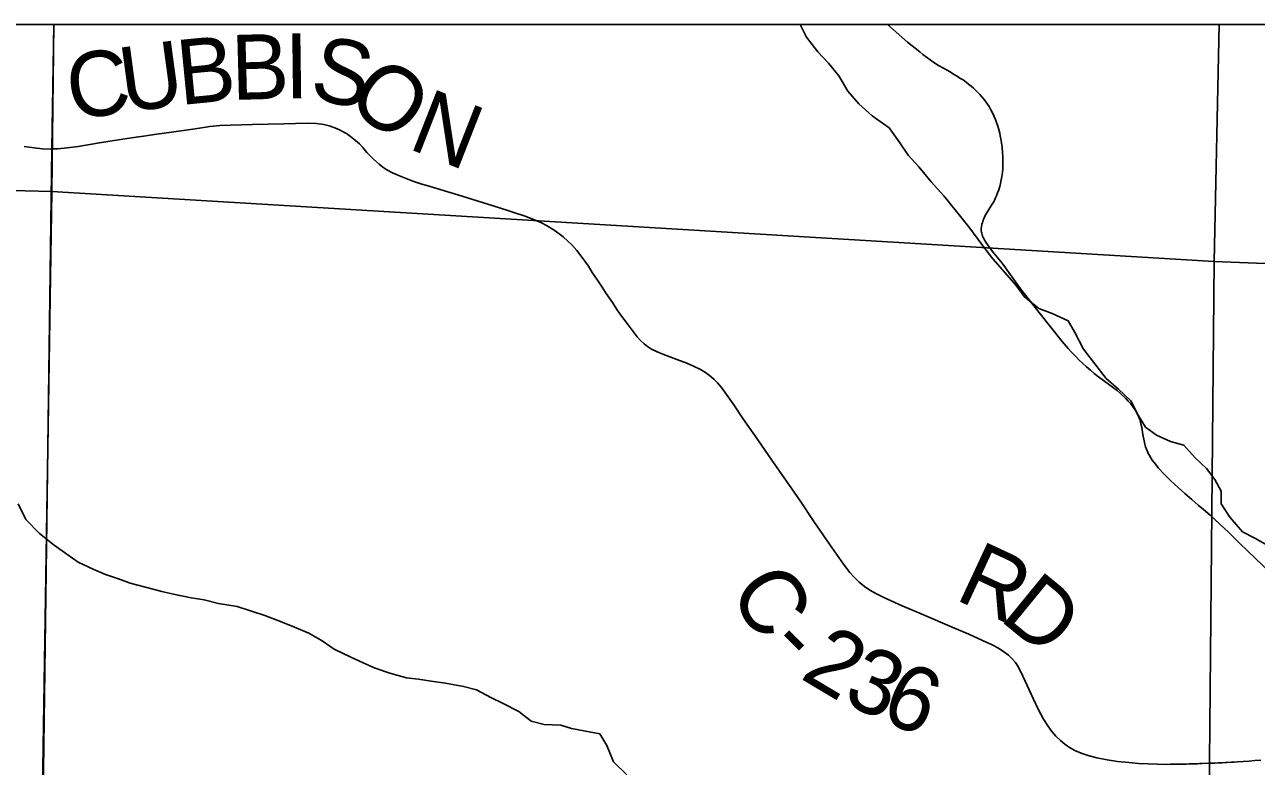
# Model space of a CAD drawing. Extents: x 0 to 34, y 0 to 22.
# Drawn here: x 3.363 to 4.44, y 20.252 to 20.9 of the extents above; entities that cross this region are included whole.
import ezdxf

# ---------------------------------------------------------------- set-up
doc = ezdxf.new("R2010")
doc.units = 0
for name, color, linetype in [('GM_X_Corporation', 7, 'Continuous'), ('GM_X_County_Road', 7, 'Continuous'), ('GM_X_County_Road_Text', 7, 'Continuous'), ('GM_X_Minor_River', 7, 'Continuous'), ('SH_Data', 7, 'Continuous')]:
    doc.layers.add(name, color=color, linetype=linetype)

msp = doc.modelspace()

# ---------------------------------------------------------------- linework, layer by layer
at = {"layer": 'GM_X_Corporation'}
for points in [[(8.9, 20.9), (2.1, 20.9), (2.1, 15.6606)], [(5.3543, 16.3597), (5.3699, 17.5116), (5.3717, 17.6123), (4.6401, 17.6298), (4.3705, 17.6391), (4.3669, 17.8198), (4.37, 17.9048), (4.3768, 18.4091), (4.3782, 18.6502), (4.377, 18.6713), (3.7035, 18.69), (3.3642, 18.7005), (3.3691, 19.5041), (3.3724, 19.7263), (3.3869, 20.7918), (3.3886, 20.9), (2.1, 20.9), (2.1, 15.6606)], [(8.9, 20.9), (3.3886, 20.9), (3.3869, 20.7918), (3.3724, 19.7263), (3.3691, 19.5041), (3.3642, 18.7005)]]:
    msp.add_lwpolyline(points, dxfattribs=at)
for points in [[(3.3885, 20.9), (2.378, 20.9), (2.3781, 20.7796), (3.3867, 20.754)], [(4.4076, 20.9), (3.3885, 20.9), (3.3867, 20.754), (4.4032, 20.6929)], [(5.4364, 20.9), (4.4076, 20.9), (4.4032, 20.6929), (5.4344, 20.6525)], [(3.3867, 20.754), (3.3708, 19.7265), (2.3578, 19.7506), (2.3781, 20.7796)], [(3.3867, 20.754), (4.4032, 20.6929), (4.3939, 19.6935), (3.3708, 19.7265)], [(5.4344, 20.6525), (5.4328, 20.6183), (5.4095, 19.6556), (4.3939, 19.6935), (4.4032, 20.6929)]]:
    msp.add_lwpolyline(points, close=True, dxfattribs=at)
at = {"layer": 'GM_X_County_Road'}
for points in [[(4.4522, 20.4211), (4.4256, 20.4464), (4.416, 20.456), (4.4078, 20.4636), (4.3995, 20.471), (4.3939, 20.476), (4.3892, 20.48), (4.3835, 20.4849), (4.3775, 20.4901), (4.3715, 20.4954), (4.3653, 20.5011), (4.3593, 20.5069), (4.3545, 20.5121), (4.3506, 20.5171), (4.349, 20.5192), (4.3477, 20.5212), (4.3466, 20.5232), (4.3455, 20.5251), (4.3447, 20.5269), (4.3439, 20.5288), (4.3432, 20.5309), (4.3425, 20.5332), (4.3419, 20.536), (4.3408, 20.5417), (4.3399, 20.5477), (4.3394, 20.5499), (4.3388, 20.5525), (4.3381, 20.5547), (4.3373, 20.5567), (4.3364, 20.5587), (4.3354, 20.5607), (4.3344, 20.5625), (4.3331, 20.5644), (4.3301, 20.5684), (4.328, 20.5709), (4.3259, 20.5731), (4.3213, 20.5774), (4.3183, 20.5801), (4.3151, 20.5826), (4.3021, 20.5921), (4.2983, 20.5951), (4.2949, 20.5979), (4.2915, 20.6008), (4.2884, 20.6036), (4.2852, 20.6067), (4.2818, 20.6101), (4.2784, 20.6137), (4.2755, 20.6169), (4.2703, 20.623), (4.2509, 20.6472), (4.2338, 20.669), (4.2177, 20.6914), (4.2105, 20.7003), (4.2076, 20.7039), (4.2047, 20.708), (4.2029, 20.7107), (4.202, 20.7123), (4.2012, 20.7138), (4.2006, 20.7151), (4.2002, 20.7165), (4.1999, 20.7176), (4.1997, 20.7187), (4.1995, 20.7198), (4.1995, 20.7209), (4.1995, 20.7219), (4.1996, 20.7229), (4.1997, 20.7239), (4.1999, 20.7249), (4.2001, 20.7259), (4.2004, 20.7268), (4.2007, 20.7278), (4.201, 20.7287), (4.2014, 20.7298), (4.2019, 20.7309), (4.2027, 20.7326), (4.2038, 20.7346), (4.2085, 20.7423), (4.2106, 20.7458), (4.2117, 20.748), (4.2128, 20.7503), (4.2138, 20.7529), (4.2147, 20.7555), (4.2156, 20.7584), (4.2163, 20.7611), (4.217, 20.7642), (4.2175, 20.7673), (4.218, 20.7708), (4.2183, 20.7739), (4.2184, 20.7773), (4.2184, 20.7811), (4.2183, 20.7846), (4.2181, 20.7882), (4.2177, 20.7927), (4.2172, 20.7966), (4.2166, 20.8002), (4.2161, 20.8027), (4.2156, 20.8051), (4.2148, 20.8083), (4.214, 20.8111), (4.2129, 20.8144), (4.2119, 20.8171), (4.2108, 20.8197), (4.2096, 20.8222), (4.2079, 20.8255), (4.2063, 20.8283), (4.2048, 20.8305), (4.2034, 20.8325), (4.2019, 20.8345), (4.2001, 20.8368), (4.1983, 20.8389), (4.1961, 20.8411), (4.1945, 20.8427), (4.1926, 20.8445), (4.1907, 20.8462), (4.1887, 20.8478), (4.1862, 20.8497), (4.1836, 20.8516), (4.1808, 20.8533), (4.1778, 20.8552), (4.1752, 20.8568), (4.1722, 20.8586), (4.1665, 20.8618), (4.1622, 20.8643), (4.1581, 20.867), (4.1548, 20.8693), (4.1515, 20.8716), (4.1485, 20.8738), (4.1456, 20.8761), (4.1351, 20.8848), (4.1174, 20.9)], [(4.444, 20.257), (4.4387, 20.2566), (4.4338, 20.2562), (4.4285, 20.2558), (4.4236, 20.2554), (4.4207, 20.2553), (4.4183, 20.2552), (4.4141, 20.2549), (4.4129, 20.2548), (4.4101, 20.2547), (4.4084, 20.2546), (4.4066, 20.2545), (4.4037, 20.2544), (4.3994, 20.2542), (4.3927, 20.254), (4.3903, 20.2539), (4.3885, 20.2538), (4.386, 20.2537), (4.3848, 20.2537), (4.3811, 20.2536), (4.3787, 20.2535), (4.3756, 20.2535), (4.3726, 20.2534), (4.3689, 20.2534), (4.3648, 20.2533), (4.3614, 20.2532), (4.3537, 20.2534), (4.3453, 20.2537), (4.3369, 20.2541), (4.3284, 20.2548), (4.3186, 20.2559), (4.3095, 20.2573), (4.3004, 20.259), (4.2939, 20.2606), (4.2869, 20.263), (4.2813, 20.2654), (4.2765, 20.2681), (4.2725, 20.2709), (4.2687, 20.274), (4.2648, 20.2778), (4.2612, 20.282), (4.2576, 20.287), (4.254, 20.2927), (4.2495, 20.3009), (4.2447, 20.3109), (4.2397, 20.3223), (4.2342, 20.3342), (4.2314, 20.3391), (4.2293, 20.3423), (4.2268, 20.3452), (4.2232, 20.3487), (4.2192, 20.3517), (4.2145, 20.3548), (4.2089, 20.3577), (4.2005, 20.3617), (4.1886, 20.367), (4.176, 20.3724), (4.1469, 20.3849), (4.1303, 20.392), (4.1144, 20.3991), (4.1073, 20.4026), (4.1019, 20.4057), (4.0973, 20.4088), (4.0926, 20.4126), (4.0882, 20.4168), (4.0845, 20.421), (4.079, 20.4284), (4.0669, 20.4457), (4.0532, 20.4657), (4.0411, 20.4837), (4.0311, 20.498), (4.0169, 20.5184), (4.0035, 20.5378), (3.9911, 20.5556), (3.9831, 20.5675), (3.9768, 20.5767), (3.9724, 20.5827), (3.9687, 20.5869), (3.9656, 20.5901), (3.9618, 20.5933), (3.9583, 20.5959), (3.954, 20.5985), (3.9478, 20.6015), (3.9421, 20.6041), (3.9333, 20.6073), (3.9211, 20.6118), (3.9154, 20.6142), (3.9111, 20.6164), (3.9075, 20.6187), (3.9046, 20.621), (3.9016, 20.6239), (3.8987, 20.6271), (3.8907, 20.6374), (3.8851, 20.6448), (3.8809, 20.6509), (3.8769, 20.6571), (3.8755, 20.6591), (3.871, 20.6658), (3.868, 20.6705), (3.8646, 20.6757), (3.8614, 20.6803), (3.8593, 20.6833), (3.8559, 20.6887), (3.8529, 20.6932), (3.8488, 20.6987), (3.8457, 20.7026), (3.8411, 20.7078), (3.838, 20.7108), (3.8338, 20.7146), (3.8268, 20.7198), (3.8199, 20.7242), (3.8143, 20.727), (3.8074, 20.7299), (3.7999, 20.7328), (3.7917, 20.7354), (3.7864, 20.7371), (3.7781, 20.7398), (3.768, 20.7429), (3.7419, 20.7511), (3.7146, 20.7593), (3.7102, 20.7605), (3.7023, 20.7632), (3.6908, 20.7677), (3.6846, 20.7703), (3.6798, 20.773), (3.6762, 20.7753), (3.6729, 20.7779), (3.6679, 20.7825), (3.6623, 20.7882), (3.6587, 20.7925), (3.6557, 20.7957), (3.6524, 20.7986), (3.648, 20.8022), (3.6443, 20.8047), (3.6416, 20.8063), (3.6382, 20.808), (3.6342, 20.8097), (3.6294, 20.8114), (3.6246, 20.8126), (3.6181, 20.8136), (3.6099, 20.8139), (3.5895, 20.8134), (3.5622, 20.8128), (3.543, 20.8122), (3.5337, 20.8117), (3.5249, 20.8108), (3.5159, 20.8095), (3.5081, 20.8084), (3.4915, 20.8061), (3.4787, 20.8041), (3.467, 20.8024), (3.4565, 20.8009), (3.4375, 20.7981), (3.4283, 20.7967), (3.4099, 20.7936), (3.4001, 20.7922), (3.3921, 20.7914), (3.3872, 20.7913), (3.3854, 20.7912), (3.3786, 20.7914), (3.3712, 20.7922), (3.3627, 20.7936)]]:
    msp.add_lwpolyline(points, dxfattribs=at)
at = {"layer": 'GM_X_Minor_River'}
for points in [[(4.3367, 20.5587), (4.3302, 20.5712), (4.3195, 20.5813), (4.3088, 20.5906), (4.2889, 20.6162), (4.2809, 20.6313), (4.2755, 20.6411), (4.2615, 20.6474), (4.2497, 20.6518), (4.2371, 20.6623), (4.2299, 20.672), (4.218, 20.6855), (4.2096, 20.6953), (4.2001, 20.7077), (4.1894, 20.722), (4.1779, 20.7367), (4.1668, 20.7502), (4.1557, 20.7626), (4.145, 20.7757), (4.1355, 20.7858), (4.1278, 20.7975), (4.119, 20.8099), (4.1042, 20.8204), (4.0924, 20.8309), (4.0828, 20.8417), (4.0748, 20.8553), (4.066, 20.8662), (4.0565, 20.8763), (4.0465, 20.8891), (4.041, 20.9)], [(4.45, 20.4447), (4.4386, 20.4511), (4.4279, 20.4566), (4.4169, 20.4694), (4.4092, 20.4811), (4.4091, 20.492), (4.4037, 20.5022), (4.3965, 20.512), (4.3865, 20.5214), (4.3766, 20.5322), (4.3649, 20.5355), (4.3527, 20.5411), (4.3432, 20.5482), (4.3367, 20.5587)], [(3.8896, 20.2441), (3.8778, 20.2554), (3.872, 20.2697), (3.8659, 20.2799), (3.8518, 20.2827), (3.8412, 20.2845), (3.8318, 20.2875), (3.8174, 20.2881), (3.806, 20.291), (3.795, 20.2996), (3.7813, 20.3066), (3.7707, 20.3118), (3.7582, 20.3185), (3.7468, 20.3214), (3.7309, 20.3243), (3.7184, 20.326), (3.7074, 20.3278), (3.6968, 20.3289), (3.6824, 20.3329), (3.6695, 20.3373), (3.6589, 20.3421), (3.6475, 20.3473), (3.6335, 20.354), (3.6232, 20.3614), (3.6114, 20.3681), (3.5989, 20.3733), (3.5868, 20.3781), (3.5731, 20.3833), (3.5614, 20.3873), (3.5489, 20.3913), (3.5326, 20.3938), (3.5201, 20.3971), (3.5087, 20.3989), (3.4932, 20.4021), (3.483, 20.4043), (3.4686, 20.4083), (3.4553, 20.4116), (3.4451, 20.4156), (3.4337, 20.4193), (3.4234, 20.4237), (3.4098, 20.43), (3.3999, 20.4371), (3.3889, 20.445), (3.3759, 20.4551), (3.3641, 20.4674), (3.3572, 20.481)]]:
    msp.add_lwpolyline(points, dxfattribs=at)
at = {"layer": 'SH_Data'}
msp.add_line((2.1, 20.9), (8.9, 20.9), dxfattribs=at)

# ---------------------------------------------------------------- texts
at = {"layer": 'GM_X_County_Road_Text'}
for s, rotation, p in [('U', 7.7391, (3.4499, 20.823)), ('B', 5.6135, (3.4989, 20.8296)), ('B', 1.5282, (3.5442, 20.8341)), ('I', 0.7416, (3.5907, 20.8354)), ('S', 348.1389, (3.6107, 20.836)), ('C', 7.8657, (3.4037, 20.8166)), ('O', 322.6303, (3.6422, 20.8309)), ('N', 338.6114, (3.697, 20.7921)), ('R', 334.9903, (4.1752, 20.3981)), ('C', 303.3534, (3.9777, 20.4037)), ('D', 320.6902, (4.2143, 20.3803)), ('-', 315.0444, (4.0113, 20.355)), ('2', 329.229, (4.0399, 20.3291)), ('3', 336.2718, (4.0768, 20.3077)), ('6', 336.6674, (4.1092, 20.2934))]:
    msp.add_text(s, height=0.0568, rotation=rotation, dxfattribs=at).set_placement(p)

doc.saveas('drawing.dxf')
